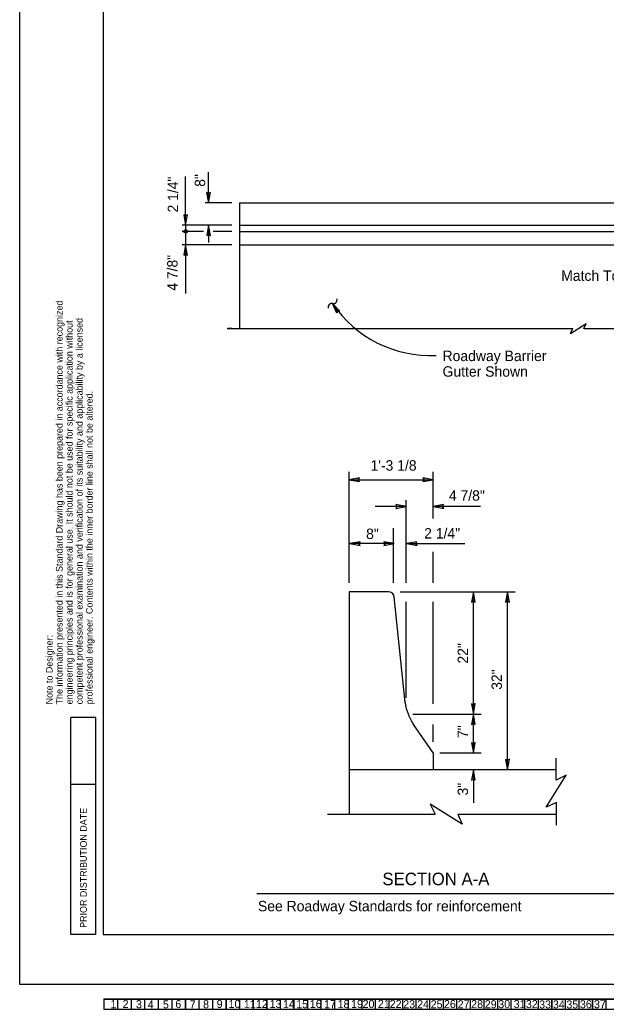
# Model space of a CAD drawing. Extents: x 0 to 2.83, y -0.03 to 1.83.
# Drawn here: x 0 to 0.732, y -0.031 to 1.205 of the extents above; entities that cross this region are included whole.
import ezdxf

# ---------------------------------------------------------------- set-up
doc = ezdxf.new("R2010")
doc.units = 0
for name, color, linetype in [('1', 7, 'Continuous'), ('10', 7, 'Continuous'), ('11', 7, 'Continuous'), ('12', 7, 'Continuous'), ('13', 7, 'Continuous'), ('14', 7, 'Continuous'), ('15', 7, 'Continuous'), ('16', 7, 'Continuous'), ('17', 7, 'Continuous'), ('18', 7, 'Continuous'), ('19', 7, 'Continuous'), ('2', 7, 'Continuous'), ('20', 7, 'Continuous'), ('21', 7, 'Continuous'), ('22', 7, 'Continuous'), ('23', 7, 'Continuous'), ('24', 7, 'Continuous'), ('25', 7, 'Continuous'), ('26', 7, 'Continuous'), ('27', 7, 'Continuous'), ('28', 7, 'Continuous'), ('29', 7, 'Continuous'), ('3', 7, 'Continuous'), ('30', 7, 'Continuous'), ('31', 7, 'Continuous'), ('32', 7, 'Continuous'), ('33', 7, 'Continuous'), ('34', 7, 'Continuous'), ('35', 7, 'Continuous'), ('36', 7, 'Continuous'), ('37', 7, 'Continuous'), ('4', 7, 'Continuous'), ('40', 7, 'Continuous'), ('5', 7, 'Continuous'), ('50', 7, 'Continuous'), ('54', 7, 'Continuous'), ('55', 7, 'Continuous'), ('57', 7, 'Continuous'), ('6', 7, 'Continuous'), ('62', 7, 'Continuous'), ('63', 7, 'Continuous'), ('7', 7, 'Continuous'), ('8', 7, 'Continuous'), ('9', 7, 'Continuous')]:
    doc.layers.add(name, color=color, linetype=linetype)

msp = doc.modelspace()

# ---------------------------------------------------------------- linework, layer by layer
at = {"layer": '40'}
for p, q in [((0.2743, 0.9762), (0.2743, 0.8195)), ((0.2743, 0.9762), (0.8822, 0.9762)), ((0.2743, 0.9484), (0.8822, 0.9484)), ((0.2743, 0.9406), (0.8822, 0.9406)), ((0.2743, 0.9237), (0.8822, 0.9237))]:
    msp.add_line(p, q, dxfattribs=at)
at = {"layer": '50'}
for p, q in [((0.4603, 0.4905), (0.411, 0.4905)), ((0.411, 0.4905), (0.411, 0.2683)), ((0.4808, 0.3521), (0.4672, 0.4843)), ((0.5161, 0.2892), (0.4912, 0.3249)), ((0.5161, 0.2892), (0.5161, 0.2683)), ((0.6693, 0.2683), (0.411, 0.2683)), ((0.411, 0.2683), (0.411, 0.2128))]:
    msp.add_line(p, q, dxfattribs=at)
for centre, radius, start, end in [((0.4603, 0.4836), 0.00694, 5.8395, 90), ((0.5494, 0.3628), 0.0694, 188.8949, 213.1061)]:
    msp.add_arc(centre, radius, start, end, dxfattribs=at)
at = {"layer": '54'}
for points in [[(0.2356, 0.9762), (0.238, 0.9892), (0.2356, 0.9877), (0.2332, 0.9891)], [(0.207, 0.9484), (0.2094, 0.9614), (0.207, 0.9599), (0.2046, 0.9613)], [(0.2356, 0.9484), (0.2333, 0.9355), (0.2356, 0.937), (0.238, 0.9356)], [(0.207, 0.9237), (0.2046, 0.9107), (0.207, 0.9122), (0.2094, 0.9109)], [(0.411, 0.6305), (0.424, 0.6282), (0.4225, 0.6305), (0.4239, 0.6329)], [(0.5161, 0.6305), (0.5031, 0.6329), (0.5046, 0.6305), (0.5032, 0.6281)], [(0.4822, 0.5971), (0.4692, 0.5995), (0.4707, 0.5971), (0.4694, 0.5947)], [(0.5161, 0.5971), (0.5291, 0.5947), (0.5276, 0.5971), (0.5289, 0.5995)], [(0.4117, 0.5506), (0.4247, 0.5483), (0.4232, 0.5506), (0.4246, 0.553)], [(0.4673, 0.5506), (0.4543, 0.553), (0.4558, 0.5506), (0.4544, 0.5482)], [(0.4829, 0.5506), (0.4959, 0.5483), (0.4944, 0.5506), (0.4957, 0.553)], [(0.5661, 0.4905), (0.5637, 0.4775), (0.5661, 0.4791), (0.5685, 0.4777)], [(0.6086, 0.4905), (0.6062, 0.4775), (0.6086, 0.4791), (0.611, 0.4777)], [(0.5661, 0.3378), (0.5685, 0.3508), (0.5661, 0.3492), (0.5637, 0.3506)], [(0.5661, 0.3378), (0.5637, 0.3248), (0.5661, 0.3263), (0.5685, 0.3249)], [(0.5661, 0.2892), (0.5685, 0.3021), (0.5661, 0.3006), (0.5637, 0.302)], [(0.6086, 0.2683), (0.611, 0.2813), (0.6086, 0.2798), (0.6062, 0.2812)], [(0.5661, 0.2683), (0.5637, 0.2553), (0.5661, 0.2568), (0.5685, 0.2555)]]:
    msp.add_lwpolyline(points, close=True, dxfattribs=at)
at = {"layer": '55'}
for p, q in [((0.2356, 0.9762), (0.2356, 1.0146)), ((0.207, 0.9484), (0.207, 1.0091)), ((0.2647, 0.9762), (0.2315, 0.9762)), ((0.2647, 0.9484), (0.2028, 0.9484)), ((0.2294, 0.9406), (0.2028, 0.9406)), ((0.207, 0.9484), (0.207, 0.9237)), ((0.2356, 0.9484), (0.2356, 0.9265)), ((0.2647, 0.9406), (0.2414, 0.9406)), ((0.2647, 0.9237), (0.2028, 0.9237)), ((0.207, 0.9237), (0.207, 0.8629)), ((0.2587, 0.8194), (0.6796, 0.8194)), ((0.2647, 0.8195), (0.2595, 0.8195)), ((0.6743, 0.8193), (0.6902, 0.8193)), ((0.6871, 0.8131), (0.707, 0.8255)), ((0.6871, 0.8131), (0.6902, 0.8193)), ((0.7039, 0.8193), (0.707, 0.8255)), ((0.7039, 0.8193), (0.7198, 0.8193)), ((0.7078, 0.8194), (1.4038, 0.8194)), ((0.411, 0.5016), (0.411, 0.6402)), ((0.411, 0.6305), (0.5161, 0.6305)), ((0.5161, 0.582), (0.5161, 0.6402)), ((0.4822, 0.5971), (0.4434, 0.5971)), ((0.4822, 0.5016), (0.4822, 0.6049)), ((0.5749, 0.5971), (0.5161, 0.5971)), ((0.4666, 0.5016), (0.4666, 0.57)), ((0.4673, 0.5506), (0.4117, 0.5506)), ((0.4829, 0.5506), (0.5555, 0.5506)), ((0.5161, 0.5016), (0.5161, 0.5403)), ((0.4749, 0.4905), (0.6184, 0.4905)), ((0.5661, 0.3378), (0.5661, 0.4905)), ((0.6086, 0.2683), (0.6086, 0.4905)), ((0.4822, 0.358), (0.4822, 0.4778)), ((0.5161, 0.3507), (0.5161, 0.4778)), ((0.4904, 0.3378), (0.5757, 0.3378)), ((0.5661, 0.2892), (0.5661, 0.3378)), ((0.5161, 0.3032), (0.5161, 0.3248)), ((0.5241, 0.2892), (0.5757, 0.2892)), ((0.6693, 0.2553), (0.6693, 0.2829)), ((0.5661, 0.2683), (0.5661, 0.2271)), ((0.657, 0.2215), (0.6818, 0.2615)), ((0.6818, 0.2615), (0.6693, 0.2553)), ((0.5522, 0.2004), (0.5122, 0.2253)), ((0.5122, 0.2253), (0.5185, 0.2128)), ((0.6697, 0.2273), (0.657, 0.2215)), ((0.6697, 0.1989), (0.6697, 0.2273)), ((0.3842, 0.2128), (0.5185, 0.2128)), ((0.5467, 0.2128), (0.5522, 0.2004)), ((0.5467, 0.2128), (0.6697, 0.2128))]:
    msp.add_line(p, q, dxfattribs=at)
for points in [[(0.3903, 0.8505), (0.3995, 0.8411), (0.3973, 0.841), (0.392, 0.848), (0.3965, 0.8404), (0.3956, 0.8384), (0.3903, 0.8505)], [(0.3935, 0.8468), (0.3973, 0.8417), (0.3983, 0.8417), (0.3911, 0.8493), (0.3955, 0.8397), (0.3959, 0.8408), (0.3927, 0.8459)]]:
    msp.add_lwpolyline(points, dxfattribs=at)
msp.add_circle((0.207, 0.9406), 0.00214, dxfattribs=at)
for centre, radius, start, end in [((0.3913, 0.8551), 0.0047, 258.7125, 15.1185), ((0.3894, 0.8459), 0.0047, 78.7125, 195.1185), ((0.5124, 0.9329), 0.1473, 214.0105, 272.8594)]:
    msp.add_arc(centre, radius, start, end, dxfattribs=at)
at = {"layer": '57'}
msp.add_line((0.7871, 0.1135), (0.296, 0.1135), dxfattribs=at)
at = {"layer": '62'}
for p, q in [((0.1049, -0.018), (1.1717, -0.018)), ((0.1049, -0.018), (0.1049, -0.0307)), ((0.105, -0.0181), (1.1718, -0.0181)), ((0.105, -0.0181), (0.105, -0.0308)), ((0.1219, -0.018), (0.1219, -0.0307)), ((0.1219, -0.0181), (0.1219, -0.0308)), ((0.1388, -0.018), (0.1388, -0.0307)), ((0.1388, -0.0181), (0.1388, -0.0308)), ((0.1557, -0.018), (0.1557, -0.0307)), ((0.1558, -0.0181), (0.1558, -0.0308)), ((0.1727, -0.018), (0.1727, -0.0307)), ((0.1727, -0.0181), (0.1727, -0.0308)), ((0.1896, -0.018), (0.1896, -0.0307)), ((0.1896, -0.0181), (0.1896, -0.0308)), ((0.2065, -0.018), (0.2065, -0.0307)), ((0.2066, -0.0181), (0.2066, -0.0308)), ((0.2235, -0.018), (0.2235, -0.0307)), ((0.2235, -0.0181), (0.2235, -0.0308)), ((0.2404, -0.018), (0.2404, -0.0307)), ((0.2404, -0.0181), (0.2404, -0.0308)), ((0.2573, -0.018), (0.2573, -0.0307)), ((0.2574, -0.0181), (0.2574, -0.0308)), ((0.2743, -0.018), (0.2743, -0.0307)), ((0.2743, -0.0181), (0.2743, -0.0308)), ((0.2912, -0.018), (0.2912, -0.0307)), ((0.2912, -0.0181), (0.2912, -0.0308)), ((0.3081, -0.018), (0.3081, -0.0307)), ((0.3082, -0.0181), (0.3082, -0.0308)), ((0.3251, -0.018), (0.3251, -0.0307)), ((0.3251, -0.0181), (0.3251, -0.0308)), ((0.342, -0.018), (0.342, -0.0307)), ((0.342, -0.0181), (0.342, -0.0308)), ((0.3589, -0.018), (0.3589, -0.0307)), ((0.359, -0.0181), (0.359, -0.0308)), ((0.3759, -0.018), (0.3759, -0.0307)), ((0.3759, -0.0181), (0.3759, -0.0308)), ((0.3928, -0.018), (0.3928, -0.0307)), ((0.3928, -0.0181), (0.3928, -0.0308)), ((0.4097, -0.018), (0.4097, -0.0307)), ((0.4098, -0.0181), (0.4098, -0.0308)), ((0.4267, -0.018), (0.4267, -0.0307)), ((0.4267, -0.0181), (0.4267, -0.0308)), ((0.4436, -0.018), (0.4436, -0.0307)), ((0.4436, -0.0181), (0.4436, -0.0308)), ((0.4605, -0.018), (0.4605, -0.0307)), ((0.4606, -0.0181), (0.4606, -0.0308)), ((0.4775, -0.018), (0.4775, -0.0307)), ((0.4775, -0.0181), (0.4775, -0.0308)), ((0.4944, -0.018), (0.4944, -0.0307)), ((0.4944, -0.0181), (0.4944, -0.0308)), ((0.5113, -0.018), (0.5113, -0.0307)), ((0.5114, -0.0181), (0.5114, -0.0308)), ((0.5283, -0.018), (0.5283, -0.0307)), ((0.5283, -0.0181), (0.5283, -0.0308)), ((0.5452, -0.018), (0.5452, -0.0307)), ((0.5452, -0.0181), (0.5452, -0.0308)), ((0.5621, -0.018), (0.5621, -0.0307)), ((0.5622, -0.0181), (0.5622, -0.0308)), ((0.5791, -0.018), (0.5791, -0.0307)), ((0.5791, -0.0181), (0.5791, -0.0308)), ((0.596, -0.018), (0.596, -0.0307)), ((0.596, -0.0181), (0.596, -0.0308)), ((0.6129, -0.018), (0.6129, -0.0307)), ((0.613, -0.0181), (0.613, -0.0308)), ((0.6299, -0.018), (0.6299, -0.0307)), ((0.6299, -0.0181), (0.6299, -0.0308)), ((0.6468, -0.018), (0.6468, -0.0307)), ((0.6468, -0.0181), (0.6468, -0.0308)), ((0.6637, -0.018), (0.6637, -0.0307)), ((0.6638, -0.0181), (0.6638, -0.0308)), ((0.6807, -0.018), (0.6807, -0.0307)), ((0.6807, -0.0181), (0.6807, -0.0308)), ((0.6976, -0.018), (0.6976, -0.0307)), ((0.6976, -0.0181), (0.6976, -0.0308)), ((0.7145, -0.018), (0.7145, -0.0307)), ((0.7146, -0.0181), (0.7146, -0.0308)), ((0.7315, -0.018), (0.7315, -0.0307)), ((0.7315, -0.0181), (0.7315, -0.0308)), ((0.1049, -0.0307), (1.1717, -0.0307)), ((0.105, -0.0308), (1.1718, -0.0308))]:
    msp.add_line(p, q, dxfattribs=at)
at = {"layer": '63'}
for p, q in [((0, 0), (0, 1.8333)), ((0.0638, 0.0624), (0.0638, 0.3333)), ((0.0951, 0.3333), (0.0638, 0.3333)), ((0.0951, 0.0624), (0.0951, 0.3333)), ((0.0951, 0.2499), (0.0638, 0.2499)), ((0.0951, 0.0624), (0.0638, 0.0624)), ((2.8333, 0), (0, 0))]:
    msp.add_line(p, q, dxfattribs=at)
msp.add_lwpolyline([(2.7292, 1.7708), (0.1042, 1.7708), (0.1042, 0.0624), (2.7292, 0.0624)], close=True, dxfattribs=at)

# ---------------------------------------------------------------- texts
at = {"layer": '1'}
for p in [(0.1132, -0.0294), (0.1132, -0.0295)]:
    msp.add_text('1', height=0.01, rotation=360, dxfattribs=at).set_placement(p)
at = {"layer": '10'}
msp.add_text('10', height=0.01, rotation=360, dxfattribs=at).set_placement((0.2605, -0.0293))
msp.add_text('10', height=0.01, rotation=360, dxfattribs=at).set_placement((0.2605, -0.0293))
at = {"layer": '11'}
msp.add_text('11', height=0.01, rotation=360, dxfattribs=at).set_placement((0.2796, -0.0294))
msp.add_text('11', height=0.01, rotation=360, dxfattribs=at).set_placement((0.2796, -0.0294))
at = {"layer": '12'}
msp.add_text('12', height=0.01, rotation=360, dxfattribs=at).set_placement((0.2947, -0.0293))
msp.add_text('12', height=0.01, rotation=360, dxfattribs=at).set_placement((0.2947, -0.0293))
at = {"layer": '13'}
msp.add_text('13', height=0.01, rotation=360, dxfattribs=at).set_placement((0.3118, -0.0293))
msp.add_text('13', height=0.01, rotation=360, dxfattribs=at).set_placement((0.3118, -0.0293))
at = {"layer": '14'}
for p in [(0.3284, -0.0294), (0.3285, -0.0294)]:
    msp.add_text('14', height=0.01, rotation=360, dxfattribs=at).set_placement(p)
at = {"layer": '15'}
msp.add_text('15', height=0.01, rotation=360, dxfattribs=at).set_placement((0.3449, -0.0295))
msp.add_text('15', height=0.01, rotation=360, dxfattribs=at).set_placement((0.3449, -0.0295))
at = {"layer": '16'}
msp.add_text('16', height=0.01, rotation=360, dxfattribs=at).set_placement((0.3619, -0.0292))
msp.add_text('16', height=0.01, rotation=360, dxfattribs=at).set_placement((0.3619, -0.0292))
at = {"layer": '17'}
msp.add_text('17', height=0.01, rotation=360, dxfattribs=at).set_placement((0.3797, -0.0295))
msp.add_text('17', height=0.01, rotation=360, dxfattribs=at).set_placement((0.3797, -0.0295))
at = {"layer": '18'}
msp.add_text('18', height=0.01, rotation=360, dxfattribs=at).set_placement((0.3966, -0.0294))
msp.add_text('18', height=0.01, rotation=360, dxfattribs=at).set_placement((0.3966, -0.0294))
at = {"layer": '19'}
msp.add_text('19', height=0.01, rotation=360, dxfattribs=at).set_placement((0.4134, -0.0292))
msp.add_text('19', height=0.01, rotation=360, dxfattribs=at).set_placement((0.4134, -0.0292))
at = {"layer": '2'}
msp.add_text('2', height=0.01, rotation=360, dxfattribs=at).set_placement((0.1283, -0.0293))
msp.add_text('2', height=0.01, rotation=360, dxfattribs=at).set_placement((0.1283, -0.0293))
at = {"layer": '20'}
for p in [(0.4277, -0.0293), (0.4278, -0.0293)]:
    msp.add_text('20', height=0.01, rotation=360, dxfattribs=at).set_placement(p)
at = {"layer": '21'}
msp.add_text('21', height=0.01, rotation=360, dxfattribs=at).set_placement((0.4469, -0.0291))
msp.add_text('21', height=0.01, rotation=360, dxfattribs=at).set_placement((0.4469, -0.0291))
at = {"layer": '22'}
msp.add_text('22', height=0.01, rotation=360, dxfattribs=at).set_placement((0.4616, -0.0293))
msp.add_text('22', height=0.01, rotation=360, dxfattribs=at).set_placement((0.4616, -0.0293))
at = {"layer": '23'}
msp.add_text('23', height=0.01, rotation=360, dxfattribs=at).set_placement((0.4785, -0.0296))
msp.add_text('23', height=0.01, rotation=360, dxfattribs=at).set_placement((0.4785, -0.0296))
at = {"layer": '24'}
msp.add_text('24', height=0.01, rotation=360, dxfattribs=at).set_placement((0.4958, -0.0296))
msp.add_text('24', height=0.01, rotation=360, dxfattribs=at).set_placement((0.4958, -0.0296))
at = {"layer": '25'}
msp.add_text('25', height=0.01, rotation=360, dxfattribs=at).set_placement((0.5128, -0.0296))
msp.add_text('25', height=0.01, rotation=360, dxfattribs=at).set_placement((0.5128, -0.0296))
at = {"layer": '26'}
msp.add_text('26', height=0.01, rotation=360, dxfattribs=at).set_placement((0.5293, -0.0294))
msp.add_text('26', height=0.01, rotation=360, dxfattribs=at).set_placement((0.5293, -0.0294))
at = {"layer": '27'}
msp.add_text('27', height=0.01, rotation=360, dxfattribs=at).set_placement((0.5465, -0.0296))
msp.add_text('27', height=0.01, rotation=360, dxfattribs=at).set_placement((0.5465, -0.0296))
at = {"layer": '28'}
msp.add_text('28', height=0.01, rotation=360, dxfattribs=at).set_placement((0.5633, -0.0294))
msp.add_text('28', height=0.01, rotation=360, dxfattribs=at).set_placement((0.5633, -0.0294))
at = {"layer": '29'}
msp.add_text('29', height=0.01, rotation=360, dxfattribs=at).set_placement((0.5803, -0.0296))
msp.add_text('29', height=0.01, rotation=360, dxfattribs=at).set_placement((0.5803, -0.0296))
at = {"layer": '3'}
for p in [(0.145, -0.0295), (0.145, -0.0296)]:
    msp.add_text('3', height=0.01, rotation=360, dxfattribs=at).set_placement(p)
at = {"layer": '30'}
msp.add_text('30', height=0.01, rotation=360, dxfattribs=at).set_placement((0.5971, -0.0295))
msp.add_text('30', height=0.01, rotation=360, dxfattribs=at).set_placement((0.5971, -0.0295))
at = {"layer": '31'}
msp.add_text('31', height=0.01, rotation=360, dxfattribs=at).set_placement((0.6164, -0.0294))
msp.add_text('31', height=0.01, rotation=360, dxfattribs=at).set_placement((0.6164, -0.0294))
at = {"layer": '32'}
msp.add_text('32', height=0.01, rotation=360, dxfattribs=at).set_placement((0.6316, -0.0294))
msp.add_text('32', height=0.01, rotation=360, dxfattribs=at).set_placement((0.6316, -0.0294))
at = {"layer": '33'}
msp.add_text('33', height=0.01, rotation=360, dxfattribs=at).set_placement((0.6481, -0.0298))
msp.add_text('33', height=0.01, rotation=360, dxfattribs=at).set_placement((0.6481, -0.0298))
at = {"layer": '34'}
msp.add_text('34', height=0.01, rotation=360, dxfattribs=at).set_placement((0.6653, -0.0298))
msp.add_text('34', height=0.01, rotation=360, dxfattribs=at).set_placement((0.6653, -0.0298))
at = {"layer": '35'}
msp.add_text('35', height=0.01, rotation=360, dxfattribs=at).set_placement((0.6821, -0.0298))
msp.add_text('35', height=0.01, rotation=360, dxfattribs=at).set_placement((0.6821, -0.0298))
at = {"layer": '36'}
msp.add_text('36', height=0.01, rotation=360, dxfattribs=at).set_placement((0.699, -0.0296))
msp.add_text('36', height=0.01, rotation=360, dxfattribs=at).set_placement((0.699, -0.0296))
at = {"layer": '37'}
for p in [(0.7165, -0.0296), (0.7166, -0.0296)]:
    msp.add_text('37', height=0.01, rotation=360, dxfattribs=at).set_placement(p)
at = {"layer": '4'}
for p in [(0.1597, -0.0298), (0.1597, -0.0299)]:
    msp.add_text('4', height=0.01, rotation=360, dxfattribs=at).set_placement(p)
at = {"layer": '5'}
msp.add_text('5', height=0.01, rotation=360, dxfattribs=at).set_placement((0.1786, -0.0298))
msp.add_text('5', height=0.01, rotation=360, dxfattribs=at).set_placement((0.1786, -0.0298))
at = {"layer": '57'}
for s, p in [('2 1/4"', (0.1976, 0.9642)), ('8"', (0.2313, 0.9963)), ('4 7/8"', (0.1969, 0.8665)), ('22"', (0.5594, 0.4009)), ('32"', (0.6017, 0.3681)), ('7"', (0.5594, 0.3079)), ('3"', (0.5594, 0.2361))]:
    msp.add_text(s, height=0.01297, rotation=90, dxfattribs=at).set_placement(p)
for s, height, p in [('Match Toe', 0.01302, (0.6757, 0.8788)), ('Roadway Barrier', 0.013025, (0.5276, 0.7786)), ('Gutter Shown', 0.013025, (0.5276, 0.7591)), ("1'-3 1/8", 0.01302, (0.4377, 0.6418)), ('4 7/8" ', 0.01302, (0.5355, 0.6042)), ('8"', 0.01302, (0.4322, 0.5564)), ('2 1/4"', 0.01302, (0.5047, 0.557)), ('SECTION A-A', 0.015625, (0.4526, 0.1241)), ('See Roadway Standards for reinforcement', 0.013021, (0.2972, 0.0915))]:
    msp.add_text(s, height=height, dxfattribs=at).set_placement(p)
at = {"layer": '6'}
msp.add_text('6', height=0.01, rotation=360, dxfattribs=at).set_placement((0.1941, -0.0294))
msp.add_text('6', height=0.01, rotation=360, dxfattribs=at).set_placement((0.1941, -0.0294))
at = {"layer": '62'}
for s, height, p in [('The information presented in this Standard Drawing has been prepared in accordance with recognized', 0.008333, (0.0534, 0.3499)), ('engineering principles and is for general use. It should not be used for specific application without', 0.0083333, (0.0659, 0.3499)), ('competent professional examination and verification of its suitability and applicability by a licensed', 0.0083333, (0.0784, 0.3499)), ('professional engineer. Contents within the inner border line shall not be altered.', 0.008333, (0.0909, 0.3499)), ('Note to Designer:', 0.008333, (0.0409, 0.3499))]:
    msp.add_text(s, height=height, rotation=90, dxfattribs=at).set_placement(p)
at = {"layer": '63'}
msp.add_text('PRIOR DISTRIBUTION DATE', height=0.008333, rotation=90, dxfattribs=at).set_placement((0.0836, 0.0708))
at = {"layer": '7'}
for p in [(0.2121, -0.0296), (0.2121, -0.0297)]:
    msp.add_text('7', height=0.01, rotation=360, dxfattribs=at).set_placement(p)
at = {"layer": '8'}
msp.add_text('8', height=0.01, rotation=360, dxfattribs=at).set_placement((0.2287, -0.0296))
msp.add_text('8', height=0.01, rotation=360, dxfattribs=at).set_placement((0.2287, -0.0296))
at = {"layer": '9'}
for p in [(0.2457, -0.0292), (0.2457, -0.0293)]:
    msp.add_text('9', height=0.01, rotation=360, dxfattribs=at).set_placement(p)

doc.saveas('drawing.dxf')
